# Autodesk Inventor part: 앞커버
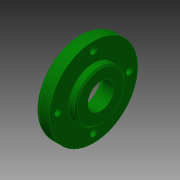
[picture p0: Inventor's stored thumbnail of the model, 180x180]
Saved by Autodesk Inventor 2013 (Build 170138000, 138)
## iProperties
Created: 2015-12
Part Number: 앞커버
Document SubType Name: Modeling
Designer: mdu
Density: 2.71 g/cm^3
Material: 알루미늄 6061
Author: mdu
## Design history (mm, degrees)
sketch "스케치1"
  geometry: L1 (-7.5, 0)-(7.5, 0); L2 (-7.5, 0)-(-7.5, 31); L3 (-7.5, 31)-(2.5, 31); L4 (2.5, 31)-(2.5, 17.5); L5 (2.5, 17.5)-(7.5, 17.5); L6 (7.5, 17.5)-(7.5, 0); 2 further points
  constraints: 12 end point, 3 perpendicular, 1 coincident, 1 horizontal, 1 midpoint, 1 parallel
  dimensions: "d0" = 15 distance of L1.start L1.end; "d1" = 62 diameter of L3 L1; "d2" = 35 diameter of L5 L1; "d5" = 10 distance of L2.end L3.end
revolve "회전1" sketch "스케치1" stored, may be unused: angle "d6" = 90 deg
sketch "스케치2" dims "d42" = 50
  geometry: 3 further points
  constraints: 2 vertical alignment, 1 coincident, 2 other
hole "구멍1" sketch "스케치2" at (0, 25) diameter "d8" = 4.5; stored, may be unused: countersink angle "d12" = 90 deg, drill point angle "d14" = 118 deg; dims "d9" = 6, "d10" = 8, "d11" = 4.4, "d13" = 8
hole "구멍2" diameter "d20" = 18; stored, may be unused: countersink angle "d24" = 90 deg, drill point angle "d26" = 0 deg; dims "d18" = 10, "d19" = 10, "d21" = 6, "d22" = 8, "d23" = 4.4, "d25" = 8
hole "구멍3" diameter "d34" = 30; stored, may be unused: countersink angle "d38" = 90 deg, drill point angle "d40" = 0 deg; dims "d32" = 10, "d33" = 10, "d35" = 6, "d36" = 4, "d37" = 2, "d39" = 7.3
fillet "모깎기1" dims "d27" = 3, "d41" = 0.3
chamfer "모따기1" distance "d29" = 1; stored, may be unused: second distance "d30" = 2, angle "d31" = 45 deg
node "솔리드1"
pattern_circular "원형 패턴1" dims angle "d16" = 360 deg
